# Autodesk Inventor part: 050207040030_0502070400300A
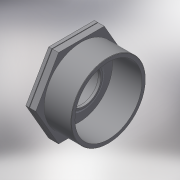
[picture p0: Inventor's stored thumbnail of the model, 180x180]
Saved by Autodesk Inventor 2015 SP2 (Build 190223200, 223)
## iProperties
Created: 2017-05
Part Number: 050207040030_0502070400300A
Material: Generic
Description: PLASSON REDUCING BUSHING 4"-3"
Document SubType Name: Modeling
Designer: KIM
Density: 1 g/cm^3
Appearance: Default
Author: KIM
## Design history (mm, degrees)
derived "050207.ipt"
feature "Solid1::050207.ipt"
tag "TaggingFeature1"
body "Solid1"
other parameters: "d1" = 113.03, "d5" = 41, "d8" = 0.56, "d12" = 0, "d15" = 56, "d19" = 0, "d30" = 9.33333, "d31" = 4.66667, "d33" = 84.926, "d34" = 101.727, "d36" = 6, "d37" = 93.4186, "d38" = 44.8, "d39" = 76.4334, "d40" = 4.1, "d41" = 0, "H_" = 56, "R_" = 113.03, "l_2" = 41, "Rp_" = 84.926
